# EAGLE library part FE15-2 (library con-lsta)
FEMALE HEADER
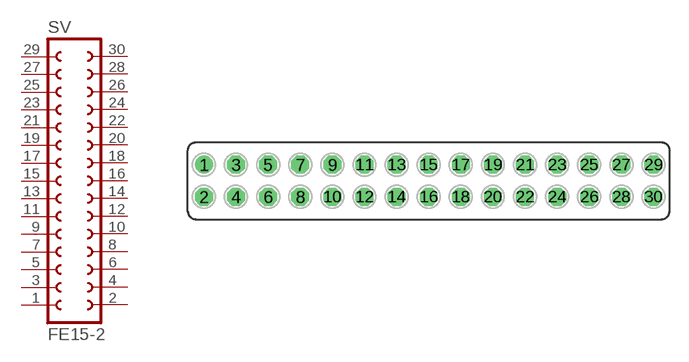
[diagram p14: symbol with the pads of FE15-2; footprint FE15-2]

Designator prefix SV

## FE15-2 (OC_FARNELL: unknown; OC_NEWARK: unknown)  [FE15-2]
1  1  pas
2  2  pas
3  3  pas
4  4  pas
5  5  pas
6  6  pas
7  7  pas
8  8  pas
9  9  pas
10  10  pas
11  11  pas
12  12  pas
13  13  pas
14  14  pas
15  15  pas
16  16  pas
17  17  pas
18  18  pas
19  19  pas
20  20  pas
21  21  pas
22  22  pas
23  23  pas
24  24  pas
25  25  pas
26  26  pas
27  27  pas
28  28  pas
29  29  pas
30  30  pas

## Footprint FE15-2 (pad centres in mm)
FEMALE HEADER
drill 0.914 round: 1 -17.78,1.27
drill 0.914 octagon: 2 -17.78,-1.27; 3 -15.24,1.27; 4 -15.24,-1.27; 5 -12.7,1.27; 6 -12.7,-1.27; 7 -10.16,1.27; 8 -10.16,-1.27; 9 -7.62,1.27; 10 -7.62,-1.27; 11 -5.08,1.27; 12 -5.08,-1.27; 13 -2.54,1.27; 14 -2.54,-1.27; 15 0,1.27; 16 0,-1.27; 17 2.54,1.27; 18 2.54,-1.27; 19 5.08,1.27; 20 5.08,-1.27; 21 7.62,1.27; 22 7.62,-1.27; 23 10.16,1.27; 24 10.16,-1.27; 25 12.7,1.27; 26 12.7,-1.27; 27 15.24,1.27; 28 15.24,-1.27; 29 17.78,1.27; 30 17.78,-1.27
